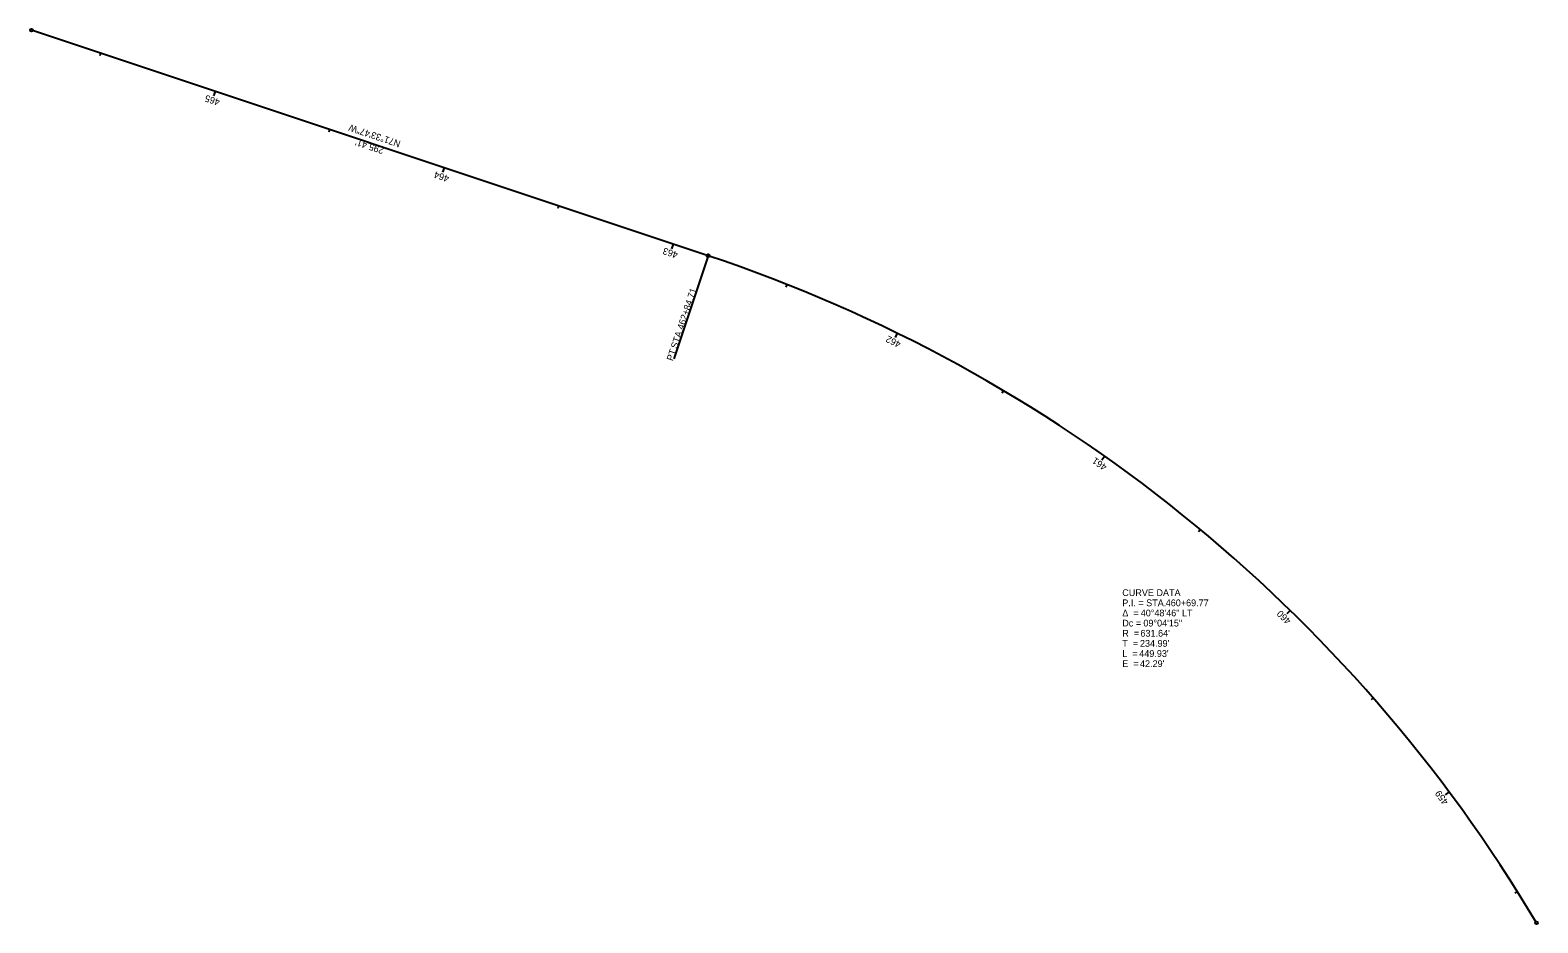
# Model space of a CAD drawing. Extents: x 124376 to 127490, y 510907 to 515083.
# Drawn here: x 125860 to 126484, y 513014 to 513384 of the extents above; entities that cross this region are included whole.
import ezdxf

# ---------------------------------------------------------------- set-up
doc = ezdxf.new("R2010")
doc.units = 0
for name, color, linetype in [('Default', 7, 'Continuous'), ('RW_X_CL', 7, 'Continuous'), ('RW_X_CL_100_Bearings', 7, 'Continuous'), ('RW_X_CL_100_Cardinal_Points', 7, 'Continuous'), ('RW_X_CL_100_Curve_Data', 7, 'Continuous'), ('RW_X_CL_100_Distances', 7, 'Continuous'), ('RW_X_CL_100_Stations', 7, 'Continuous')]:
    doc.layers.add(name, color=color, linetype=linetype)

msp = doc.modelspace()

# ---------------------------------------------------------------- linework, layer by layer
at = {"layer": 'Default'}
msp.add_line((126140.68, 513290.72), (125860.43, 513384.14), dxfattribs=at)
msp.add_arc((125940.92, 512691.49), 631.64, 30.75033, 71.5631, dxfattribs=at)
at = {"layer": 'RW_X_CL'}
msp.add_line((126140.68, 513290.72), (125860.43, 513384.14), dxfattribs=at)
msp.add_arc((125940.92, 512691.49), 631.64, 30.75033, 71.5631, dxfattribs=at)
at = {"layer": 'RW_X_CL_100_Cardinal_Points'}
msp.add_line((126140.68, 513290.72), (126126.45, 513248.03), dxfattribs=at)
for centre in [(125860.43, 513384.14), (126140.68, 513290.72), (126483.75, 513014.45)]:
    msp.add_circle(centre, 0.6, dxfattribs=at)
at = {"layer": 'RW_X_CL_100_Stations'}
for p, q in [((125889.01, 513374.62), (125888.63, 513373.48)), ((125936.44, 513358.8), (125935.81, 513356.91)), ((125983.87, 513342.99), (125983.49, 513341.85)), ((126031.31, 513327.18), (126030.67, 513325.28)), ((126078.74, 513311.36), (126078.36, 513310.23)), ((126126.17, 513295.55), (126125.54, 513293.65)), ((126173.29, 513278.84), (126172.85, 513277.72)), ((126219.01, 513258.63), (126218.13, 513256.83)), ((126262.98, 513234.86), (126262.37, 513233.83)), ((126304.94, 513207.69), (126303.79, 513206.06)), ((126344.62, 513177.29), (126343.85, 513176.36)), ((126381.77, 513143.84), (126380.37, 513142.41)), ((126416.16, 513107.57), (126415.26, 513106.77)), ((126447.57, 513068.68), (126445.97, 513067.49)), ((126475.81, 513027.44), (126474.8, 513026.8))]:
    msp.add_line(p, q, dxfattribs=at)

# ---------------------------------------------------------------- texts
at = {"layer": 'RW_X_CL_100_Bearings'}
msp.add_text('N71°33\'47"W', height=2.8, rotation=161.5631, dxfattribs=at).set_placement((126013.49, 513338.18))
at = {"layer": 'RW_X_CL_100_Cardinal_Points'}
for s, p in [('462+84.71', (126130.37, 513259.9)), (' STA. ', (126127.42, 513251.06)), ('PT', (126126.04, 513246.93))]:
    msp.add_text(s, height=2.8, rotation=71.5631, dxfattribs=at).set_placement(p)
at = {"layer": 'RW_X_CL_100_Curve_Data'}
for s, p in [('CURVE DATA', (126312.22, 513149.78)), ('Δ  = ', (126312.22, 513141.38)), ('P.I. = STA. ', (126312.22, 513145.58)), ('40°48\'46" LT', (126319.86, 513141.38)), ('460+69.77', (126330.21, 513145.58)), ('Dc = ', (126312.22, 513137.18)), ('09°04\'15"', (126320.96, 513137.18)), ('T  = ', (126312.22, 513128.78)), ('R  = ', (126312.22, 513132.98)), ("234.99'", (126319.53, 513128.78)), ("631.64'", (126319.75, 513132.98)), ('L  = ', (126312.22, 513124.58)), ("449.93'", (126319.25, 513124.58)), ('E  = ', (126312.22, 513120.38)), ("42.29'", (126319.56, 513120.38))]:
    msp.add_text(s, height=2.8, dxfattribs=at).set_placement(p)
at = {"layer": 'RW_X_CL_100_Distances'}
msp.add_text("295.41'", height=2.8, rotation=161.5631, dxfattribs=at).set_placement((126006.65, 513335.36))
at = {"layer": 'RW_X_CL_100_Stations'}
for s, rotation, p in [('465', 161.5631, (125938.69, 513355.42)), ('464', 161.5631, (126033.63, 513323.77)), ('463', 161.5631, (126128.42, 513292.17)), ('462', 153.87913, (126220.79, 513254.97)), ('461', 144.80821, (126306.13, 513203.79)), ('460', 135.7373, (126382.37, 513139.77)), ('459', 126.66638, (126447.49, 513064.6))]:
    msp.add_text(s, height=2.8, rotation=rotation, dxfattribs=at).set_placement(p)

doc.saveas('drawing.dxf')
